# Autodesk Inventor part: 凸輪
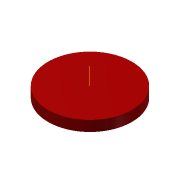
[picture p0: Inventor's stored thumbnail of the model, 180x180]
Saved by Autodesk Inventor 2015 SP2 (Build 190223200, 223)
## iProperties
Created: 2020-03
Part Number: 凸輪
Material: Stainless Steel, Austenitic
Document SubType Name: Modeling
Designer: Kuan-Lun Hsu
Manufacturer: Standard
Standards Organization: Custom
Density: 8 g/cm^3
Appearance: 平滑 - 紅色
Mass: 649.445 g
Surface Area: 195.848 cm^2
Volume: 81.1806 cm^3
CustomPartVersion: 1
Author: Kuan-Lun Hsu
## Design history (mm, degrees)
sketch "主要草圖"
  geometry: 60 further points
  constraints: 120 other
sketch "Sketch5"
  geometry: C1 r 40 at (0, 0); 1 further point
  constraints: 1 centre point, 1 coincident
  dimensions: "d9" = 80 diameter of C1
extrude "Extrusion3" new body sketch "Sketch5" stored distance "d10" = 10; taper "d11" = 0 deg
sketch "Sketch6"
  geometry: C1 r 40 at (0, 0) reference; C2 r 5 at (0, 0); 1 further point
  constraints: 1 centre point, 1 coincident
  dimensions: "d12" = 10 diameter of C2
extrude "Extrusion4" join sketch "Sketch6" distance "d13" = 20; taper "d14" = 0 deg
body "Solid2"
other parameters: "d2" = 0
